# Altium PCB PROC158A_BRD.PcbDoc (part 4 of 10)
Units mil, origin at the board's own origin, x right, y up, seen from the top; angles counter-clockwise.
Board outline 3346.45 x 4921.26 mil, 8 copper layers (Top Layer, GND1, SIG1, PWR1, PWR2, SIG2, GND2, Bottom Layer), stack 54.534 mil thick; 718 components, 459 nets, 2307 pads, 1179 vias.
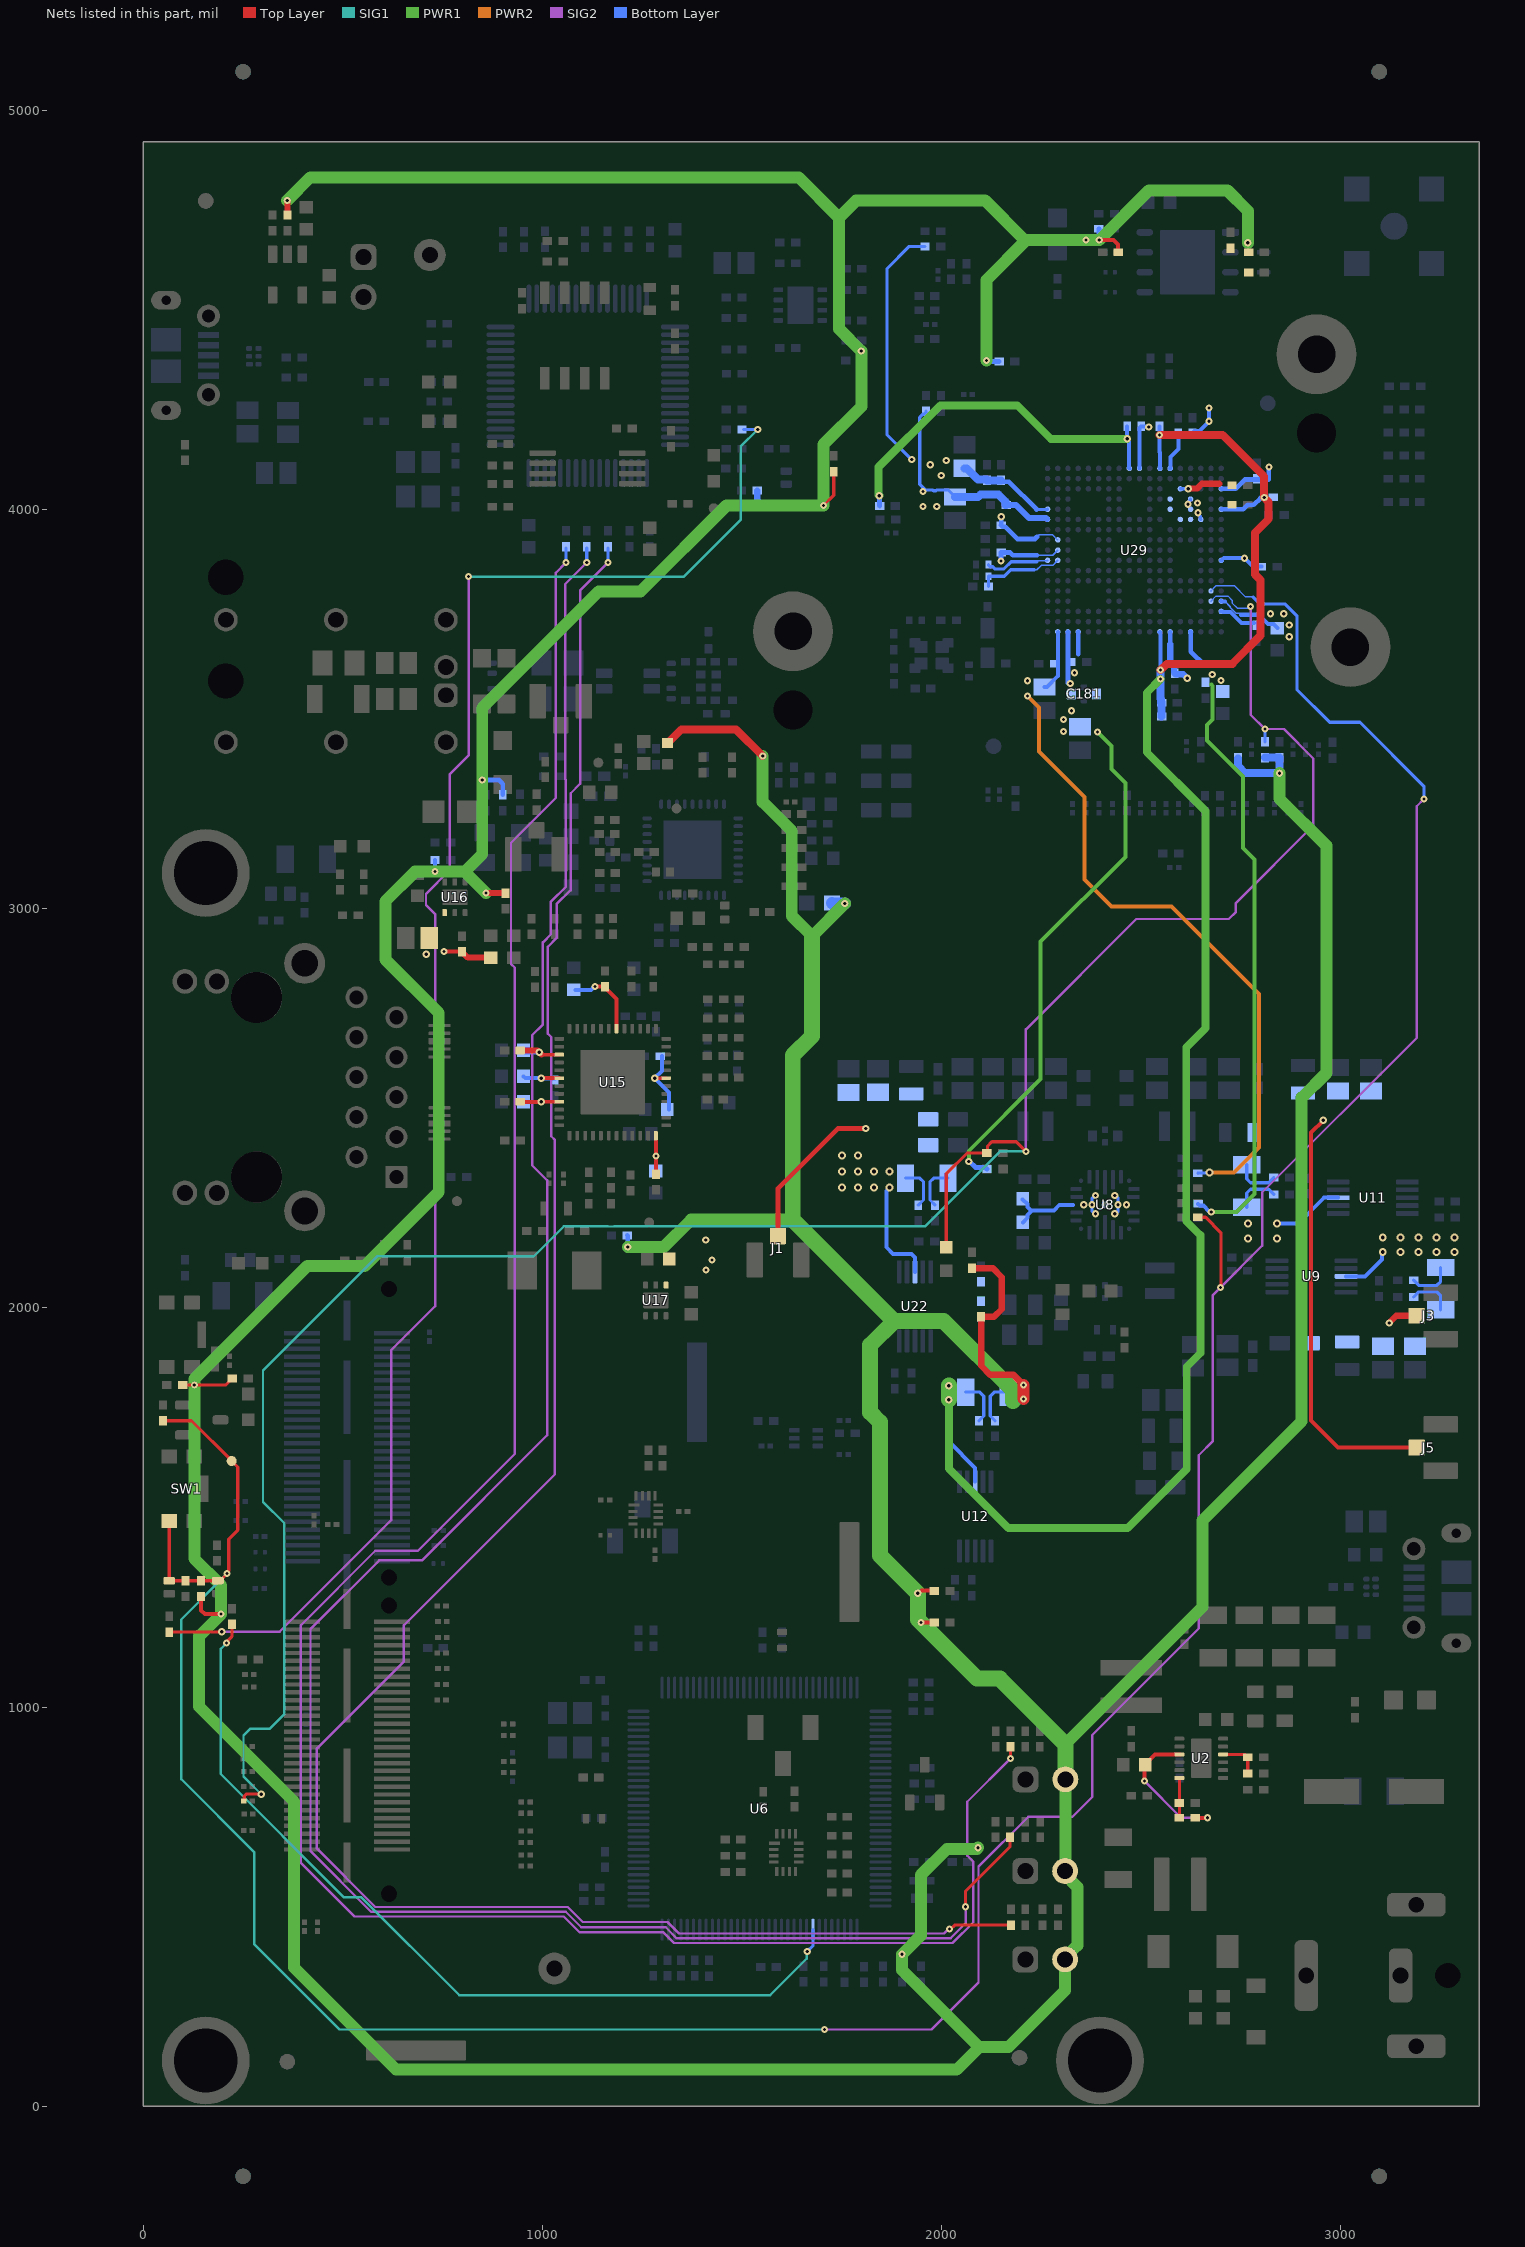
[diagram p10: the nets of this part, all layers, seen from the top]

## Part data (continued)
FB2 FB3: library part CMP-0089848-1, "600 Ohms @ 100MHz 1 Power Line Ferrite Bead 0603 (1608 Metric) 1.3A 150mOhm", Digikey Part Number=490-13259-1-ND, Impedance At Frequency="600Ω @ 100MHz", Manufacturer=Murata, Mouser Part Number=81-BLM18KG601SH1D, Operating Temperature Range="-55°C to +125°C", Test Frequency=100MHz, Tolerance_%=25%
FID1 FID2 FID3 FID4 FID5 FID6 FID7 FID8 FID9 FID10 FID11 FID12 FID13 FID14 FID15 FID16: library part CMP-0077181-1, "Fiducial mark.  There is nothing to buy or mount.", Manufacturer=N/A
J1 J3 J5: library part CMP-0091846-1, "U.FL (UMCC) Connector Jack, Male Pin 50Ohm Surface Mount Solder", Dielectric Material="Liquid Crystal Polymer", Digikey Part Number=A118077CT-ND, Frequency_Fixed=0-6GHz, Manufacturer="TE Connectivity", Mouser Part Number=571-1909763-1, Operating Temperature Range="-40°C to +90°C"
J2 J14: library part CMP-0055788-1, "UMC Straight Jack Receptacle, 50 Ohm, Gold, SMT", Manufacturer="Cinch Connectivity", Supplier Part Number 1=J983CT-ND
J4: library part CMP-0078655-1, "1 Port Header Assembly, TH", Color=Blue, Manufacturer="TE Connectivity"
J7: library part CMP-0075524-1, "Receptacle, 0.5 mm, 30x2, Gold, TH", Color=Black, Manufacturer=Samtec, Supplier Part Number 1=SAM8180-ND
J8 J10: library part CMP-0055293-1, "Connector, Receptacle, Micro-USB Type B, R/A, Bottom Mount SMT", Manufacturer=Molex, Supplier Part Number 1=WM1399CT-ND
J9: library part CMP-0088394-1, "RJ45 Connector with 1000 Base-TX Inetgrated Magnetic", Manufacturer=LINK-PP, Operating Temperature Range="-40°C to +85°C"
J12: library part CMP-0079472-1, "DC POWER JACK, R/A, TH", Color=Black, Current_A=8A, Manufacturer="CUI Inc.", Supplier Part Number 1=CP-063AH-ND, Voltage_V=24V
J13: library part CMP-0055823-2, "Connector, SMA Jack, Vertical, Gold, SMD", Color=Gold, Manufacturer="Cinch Connectivity"
J17 J18 J20 P1: library part CMP-0075405-3, "Header, 100mil, 2x1, Gold, TH", Color=Black, Current_A=6.3A, Manufacturer=Samtec, Supplier Part Number 1=SAM1029-02-ND, Voltage_V=550V
J19: library part CMP-0075524-1, "Receptacle, 0.5 mm, 30x2, Gold, TH", Color=Black, Manufacturer=Samtec, PartNumber=QSH-030-01-L-D-A, Supplier Part Number 1=SAM8180-ND
J21 J22 J23: library part CMP-0084373-1, "Header, 1x1, Gold, SMT", Color=Black, Current_A=3A, Manufacturer="Sullins Connector Solutions"
L1 L12: library part CMP-0089947-1, "100 Ohms @ 100MHz 1 Power Line Ferrite Bead 0805 (2012 Metric) 4A 20mOhm", Digikey Part Number=445-172903-1-ND, Impedance At Frequency="100Ω @ 100MHz", Manufacturer=TDK, Mouser Part Number=810-MPZ2012S101ATD25, Operating Temperature Range="-55°C to +125°C", Test Frequency=100MHz, Tolerance_%=25%
L2 L8 L9: library part CMP-0059953-1, "Inductor, 470 nH, 4 A, 0.025 ohm, SMD", Manufacturer=Cyntec, Value1="0.025 ohm", Value2=4A, ValueDisplayed=470nH
L3 L4: library part CMP-0081523-1, "Ferrite Bead, 600 ohm @ 100 MHz, 0.3 A, 0402", Manufacturer=MuRata, Supplier Part Number 1=490-3998-1-ND, Value1="0.7 ohm", Value2=0.3A, ValueDisplayed="600 ohm"
L5: library part CMP-0089502-2, "Power Inductor (SMD), 4.7 µH, 5.1 A, Shielded, 4.5 A, XAL40xx Series, 4mm x 4mm x 3.1mm", Manufacturer=Coilcraft, Mouser Part Number=994-XAL4030-472MEC, Operating Temperature Range="to +165°C", Self Resonant Frequency=36MHz, Test Frequency=1MHz, Tolerance_%=20%
L6: library part CMP-0061088-1, "Inductor, Shielded, Composite, 2.2 uH, 6.1 A, 0.0201 ohm, AEC-Q200 Grade 1, SMD", Manufacturer=Coilcraft, Value1="0.0201 ohm", Value2=6.1A, ValueDisplayed=2.2uH
L7: library part CMP-0090833-1, "100μH @ 100kHz 2 Line Common Mode Choke Surface Mount 100mA DCR 3.12Ω", Manufacturer=Murata, Mouser Part Number=81-DLW32MH101XT2L, Operating Temperature Range="-40°C to +125°C", Test Frequency=100kHz, Tolerance_%=-25/+50%
L11: library part CMP-0098175-1, "Differential Mode Choke 3.9uH 540mA 0.36Ohm 3.2x2.5x2.5mm SMT", Manufacturer=TDK, Operating Temperature Range="-40°C to +150°C", Test Frequency=100kHz, Tolerance_%=20%
LBL1: library part CMP-0003625-1, "Thermal Transfer Printable Labels, 0.650\" W x 0.200\" H - 10,000 per roll", Manufacturer=Brady, Supplier Part Number 1=97C5133
Logo1: library part CMP-0074838-1, "Texas Instrument Corporate Signature"
LOGO2: library part CMP-0074844-1
Logo3: library part CMP-0074847-1, "FCC_disclaimer"
Logo4: library part CMP-0074769-1
Logo5: library part CMP-0093808-1, Manufacturer="Texas Instruments", Operating Temperature Range=to
NT1: library part CMP-0078142-4, "Single point connection between nets.", Manufacturer=N/A
NT2 NT3 NT4: library part CMP-0078142-3, "Single point connection between nets.", Manufacturer=N/A
Q1: library part CMP-0000947-2, "MOSFET, N-CH, 100 V, 0.17 A, SOT-23", Alternate Manufacturer=None, Manufacturer="Fairchild Semiconductor", Supplier Part Number 1=BSS123NCT-ND, Value1=1, Value2="1.8 nC"
R1 R3 R4 R6 R14 R19 R20 R22 R23 R27 R28 R29 R31 R33 R35 R37 R50 R54 R55 R57 R58 R59 R62 R67 R70 R71 R76 R79 R85 R86 R87 R95 R113 R117 R128 R129 R131 R136 R146 R148 R149 R150 R151 R152 R153 R158 R162 R166 R168 R181 R186 R190 R209 R233 R241 R246 R269 R291 R295 R316 R330 R353 R354 R355 R356 R357 R358 R359 R360 R400 R401 R419: library part CMP-0026992-3, "RES, 0, 5%, 0.1 W, AEC-Q200 Grade 0, 0402", Manufacturer=Panasonic, Power_W=100mW, Supplier Part Number 1=P0.0JCT-ND, TempCo="600 ppm/C", Tolerance_%=5%, Value2=0.1W, Value_Code=0000, ValueDisplayed=0
R2: library part CMP-0026555-2, "RES, 7.50 k, 1%, 0.063 W, AEC-Q200 Grade 0, 0402", Manufacturer=Vishay-Dale, Power_W=63mW, Supplier Part Number 1=541-7.50KLCT-ND, TempCo="100 ppm/C", Tolerance_%=1%, Value2=0.063W, Value_Code=7k50, ValueDisplayed=7.50k
R5 R12 R18 R21 R24 R25 R51 R61 R72 R78 R80 R81 R82 R84 R90 R91 R94 R104 R114 R115 R135 R138 R160 R164 R165 R167 R188 R196 R197 R198 R215 R216 R218 R219 R220 R223 R224 R226 R229 R317 R318 R319 R320 R321 R322 R323 R324 R327 R328 R329 R334 R341 R344 R345 R349 R351 R361 R363 R364 R365 R366 R370 R371 R379 R390 R391 R399 R422 R423 R424 R425: library part CMP-0027008-4, "RES, 0, 5%, 0.05 W, 0201", Manufacturer=Vishay-Dale, Power_W=50mW, Supplier Part Number 1=72M6743, TempCo=ppm/C, Tolerance_%=5%, Value2=0.05W, Value_Code=0000, ValueDisplayed=0
R7 R8 R9 R10 R11 R17 R41 R43 R46 R49 R102 R125 R155 R157 R177 R184 R185 R187 R201 R222 R251 R264 R271 R272 R273 R283 R296 R299 R301 R303 R305 R309 R310 R312 R326 R335 R350 R409 R416 R417 R418: library part CMP-0025958-3, "RES, 10.0 k, 1%, 0.063 W, AEC-Q200 Grade 0, 0402", Manufacturer=Vishay-Dale, Power_W=63mW, Supplier Part Number 1=541-10.0KLCT-ND, TempCo="100 ppm/C", Tolerance_%=1%, Value2=0.063W, Value_Code=10k0, ValueDisplayed=10.0k
R13 R15 R16 R75 R92 R97 R112 R118 R132 R137 R139 R141 R142 R143 R173 R252 R253 R254 R255 R256 R257 R258 R286 R287 R288 R289: library part CMP-0026237-2, "RES, 2.49 k, 1%, 0.063 W, AEC-Q200 Grade 0, 0402", Manufacturer=Vishay-Dale, Power_W=63mW, Supplier Part Number 1=541-2.49KLCT-ND, TempCo="100 ppm/C", Tolerance_%=1%, Value2=0.063W, Value_Code=2k49, ValueDisplayed=2.49k
R26 R32 R36 R47 R56 R65 R66 R268 R348 R352 R362: library part CMP-0025964-3, "RES, 10.2, 1%, 0.063 W, AEC-Q200 Grade 0, 0402", Manufacturer=Vishay-Dale, Power_W=63mW, Supplier Part Number 1=541-10.2LCT-ND, TempCo="100 ppm/C", Tolerance_%=1%, Value2=0.063W, Value_Code=10R2, ValueDisplayed=10.2
R30 R60 R64 R346: library part CMP-0017253-2, "RES, 0.001, 1%, 1 W, AEC-Q200 Grade 0, 1206", Manufacturer="Stackpole Electronics Inc", Power_W=1W, Supplier Part Number 1=CSNL1206FT1L00CT-ND, TempCo="50 ppm/C", Tolerance_%=1%, Value_Code=1L000, ValueDisplayed=0.001
R34 R205 R280 R340 R342: library part CMP-0026890-5, "RES, 2.2 k, 5%, 0.063 W, AEC-Q200 Grade 0, 0402", Manufacturer=Vishay-Dale, Power_W=63mW, Supplier Part Number 1=541-2.2KJCT-ND, TempCo="200 ppm/C", Tolerance_%=5%, Value2=0.063W, Value_Code=2k20, ValueDisplayed=2.2k
R38: library part CMP-0026395-2, "RES, 47.5 k, 1%, 0.063 W, AEC-Q200 Grade 0, 0402", Manufacturer=Vishay-Dale, Power_W=63mW, Supplier Part Number 1=541-47.5KLCT-ND, TempCo="100 ppm/C", Tolerance_%=1%, Value2=0.063W, Value_Code=47k5, ValueDisplayed=47.5k
R39 R40 R42 R44 R45 R374 R375 R376 R377: library part CMP-0089575-2, "Res Thick Film 0201 33.2 Ohm 1% 0.05W(1/20W) ±200ppm/C Pad SMD Automotive T/R", Digikey Part Number=P122945CT-ND, Manufacturer=Panasonic, Mouser Part Number=667-ERJ-1GNF33R2C, Operating Temperature Range="-55°C to +125°C", Power_W=50mW, TempCo=200ppm/°C, Tolerance_%=1%
R48 R52 R53 R63 R106 R116 R199 R265 R270: library part CMP-0081856-1, "RES, 0, 0%, 0.2 W, AEC-Q200 Grade 0, 0402", Manufacturer=Vishay-Dale, Power_W=200mW, Supplier Part Number 1=541-0.0YBTR-ND, Tolerance_%=0%, Value2=0.2W, Value_Code=0
R68 R69: library part CMP-0026878-3, "RES, 220, 5%, 0.063 W, AEC-Q200 Grade 0, 0402", Manufacturer=Vishay-Dale, Power_W=63mW, Supplier Part Number 1=541-220JCT-ND, TempCo="200 ppm/C", Tolerance_%=5%, Value2=0.063W, Value_Code=220R, ValueDisplayed=220
R73 R183 R278 R279: library part CMP-0025950-3, "RES, 100 k, 1%, 0.063 W, AEC-Q200 Grade 0, 0402", Manufacturer=Vishay-Dale, Power_W=63mW, Supplier Part Number 1=541-100KLCT-ND, TempCo="100 ppm/C", Tolerance_%=1%, Value2=0.063W, Value_Code=100k
R74 R96 R98 R100 R101 R103 R105 R121 R122 R144 R145 R147 R169 R170 R171 R178 R179 R195 R225 R230 R234 R237 R238 R239 R240 R245 R247 R249 R290 R325 R336 R338 R339 R369 R380 R381 R386 R387 R388 R389 R413: library part CMP-0026299-2, "RES, 33.2, 1%, 0.063 W, AEC-Q200 Grade 0, 0402", Manufacturer=Vishay-Dale, Power_W=63mW, Supplier Part Number 1=541-33.2LCT-ND, TempCo="100 ppm/C", Tolerance_%=1%, Value2=0.063W, Value_Code=33R2, ValueDisplayed=33.2
R77 R93 R108 R120: library part CMP-0026699-1, "RES, 470, 1%, 0.1 W, AEC-Q200 Grade 0, 0402", Manufacturer=Panasonic, Power_W=100mW, Supplier Part Number 1=P470LCT-ND, TempCo="100 ppm/C", Tolerance_%=1%, Value2=0.1W, Value_Code=470R, ValueDisplayed=470
R83 R154 R242 R333: library part CMP-0026993-2, "RES, 100, 5%, 0.1 W, AEC-Q200 Grade 0, 0402", Manufacturer=Panasonic, Power_W=100mW, Supplier Part Number 1=P100JCT-ND, TempCo="200 ppm/C", Tolerance_%=5%, Value2=0.1W, Value_Code=100R, ValueDisplayed=100
R88 R89 R107 R109 R110 R176 R189 R192 R193 R200: library part CMP-0091690-1, "RES 0 OHM JUMPER 1/4W 0603", Digikey Part Number=HCJ0603ZT0R00CT-ND, Manufacturer="Stackpole Electronics", Operating Temperature Range="-55°C to +155°C", Power_W=250mW
R99 R123 R124 R126 R127 R133 R140 R159 R163 R315 R331: library part CMP-0026071-3, "RES, 1.00 k, 1%, 0.063 W, AEC-Q200 Grade 0, 0402", Manufacturer=Vishay-Dale, Power_W=63mW, Supplier Part Number 1=541-1.00KLCT-ND, TempCo="100 ppm/C", Tolerance_%=1%, Value2=0.063W, Value_Code=1k00, ValueDisplayed=1.00k
R111: library part CMP-0097069-1, "RES Thick Film, 4.22kΩ, 1%, 0.063W, 100ppm/°C, 0402", Manufacturer=Vishay, Operating Temperature Range="-55°C to +155°C", Power_W=63mW, TempCo=100ppm/°C, Tolerance_%=1%
R119 R130: library part CMP-0018610-3, "RES, 1.0 M, 5%, 0.25 W, AEC-Q200 Grade 0, 1206", Manufacturer=Vishay-Dale, Power_W=250mW, Supplier Part Number 1=541-1.0MECT-ND, TempCo="200 ppm/C", Tolerance_%=5%, Value2=0.25W, Value_Code=1M00, ValueDisplayed=1.0M
R134: library part CMP-0026404-2, "RES, 49.9, 1%, 0.063 W, AEC-Q200 Grade 0, 0402", Manufacturer=Vishay-Dale, Power_W=63mW, Supplier Part Number 1=541-49.9LCT-ND, TempCo="100 ppm/C", Tolerance_%=1%, Value2=0.063W, Value_Code=49R9, ValueDisplayed=49.9
R156: library part CMP-0026512-2, "RES, 6.04 k, 1%, 0.063 W, AEC-Q200 Grade 0, 0402", Manufacturer=Vishay-Dale, Power_W=63mW, Supplier Part Number 1=541-6.04KLCT-ND, TempCo="100 ppm/C", Tolerance_%=1%, Value2=0.063W, Value_Code=6k04, ValueDisplayed=6.04k
R161 R175: library part CMP-0025884-3, "RES, 0, 5%, 0.125 W, 0603", Manufacturer=Vishay/Beyschlag, Power_W=125mW, Supplier Part Number 1=MCT0603-0.0-ZZCT-ND, TempCo=ppm/C, Tolerance_%=5%, Value2=0.125W, Value_Code=0000, ValueDisplayed=0
R172: library part CMP-0025960-3, "RES, 10.5 k, 1%, 0.063 W, AEC-Q200 Grade 0, 0402", Manufacturer=Vishay-Dale, Power_W=63mW, Supplier Part Number 1=541-10.5KLCT-ND, TempCo="100 ppm/C", Tolerance_%=1%, Value2=0.063W, Value_Code=10k5, ValueDisplayed=10.5k
R174 R208: library part CMP-0078244-2, "RES, 30.0 k, 1%, 0.063 W, AEC-Q200 Grade 0, 0402", Manufacturer=Vishay-Dale, Power_W=63mW, Supplier Part Number 1=541-30.0KLCT-ND, TempCo="100 ppm/C", Tolerance_%=1%, Value2=0.063W, Value_Code=30k0, ValueDisplayed=30.0k
R180 R261 R262 R263 R266 R347: library part CMP-0078212-1, "RES, 510, 5%, 0.1 W, AEC-Q200 Grade 0, 0402", Manufacturer=Panasonic, Power_W=100mW, Supplier Part Number 1=P510JCT-ND, TempCo="200 ppm/C", Tolerance_%=5%, Value2=0.1W, Value_Code=510R, ValueDisplayed=510
R182 R206 R207: library part CMP-0020442-3, "RES, 0, 5%, 0.125 W, AEC-Q200 Grade 0, 0805", Manufacturer=Vishay-Dale, Power_W=125mW, Supplier Part Number 1=541-0.0ACT-ND, TempCo="200 ppm/C", Tolerance_%=5%, Value2=0.125W, Value_Code=0000, ValueDisplayed=0
R191: library part CMP-0091603-1, "0 Ohms Jumper 0.5W, 1/2W Chip Resistor 0805 (2012 Metric) Automotive AEC-Q200 Metal Foil", Digikey Part Number=HCJ0805ZT0R00CT-ND, Manufacturer=Stackpole, Operating Temperature Range="-55°C to +155°C", Power=500mW
R194: library part CMP-0026413-2, "RES, 4.87 k, 1%, 0.063 W, AEC-Q200 Grade 0, 0402", Manufacturer=Vishay-Dale, Power_W=63mW, Supplier Part Number 1=541-4.87KLCT-ND, TempCo="100 ppm/C", Tolerance_%=1%, Value2=0.063W, Value_Code=4k87, ValueDisplayed=4.87k
R202: library part CMP-0026403-2, "RES, 49.9 k, 1%, 0.063 W, AEC-Q200 Grade 0, 0402", Manufacturer=Vishay-Dale, Power_W=63mW, Supplier Part Number 1=541-49.9KLCT-ND, TempCo="100 ppm/C", Tolerance_%=1%, Value2=0.063W, Value_Code=49k9, ValueDisplayed=49.9k
R203: library part CMP-0026225-2, "RES, 29.4 k, 1%, 0.063 W, AEC-Q200 Grade 0, 0402", Manufacturer=Vishay-Dale, Power_W=63mW, Supplier Part Number 1=541-29.4KLCT-ND, TempCo="100 ppm/C", Tolerance_%=1%, Value2=0.063W, Value_Code=29k4, ValueDisplayed=29.4k
R204: library part CMP-0026158-2, "RES, 200 k, 1%, 0.063 W, AEC-Q200 Grade 0, 0402", Manufacturer=Vishay-Dale, Power_W=63mW, Supplier Part Number 1=541-200KLCT-ND, TempCo="100 ppm/C", Tolerance_%=1%, Value2=0.063W, Value_Code=200k
R211: library part CMP-0026468-2, "RES, 5.76 k, 1%, 0.063 W, AEC-Q200 Grade 0, 0402", Manufacturer=Vishay-Dale, Power_W=63mW, Supplier Part Number 1=541-5.76KLCT-ND, TempCo="100 ppm/C", Tolerance_%=1%, Value2=0.063W, Value_Code=5k76, ValueDisplayed=5.76k
R217 R221 R227 R228 R231 R232 R235 R236: library part CMP-0027021-3, "RES, 10, 5%, 0.05 W, 0201", Manufacturer="Yageo America", Power_W=50mW, Supplier Part Number 1=311-10NCT-ND, TempCo="350 ppm/C", Tolerance_%=5%, Value2=0.05W, Value_Code=10R0, ValueDisplayed=10
R243 R508 R512: library part CMP-0027280-3, "RES, 4.70 k, 1%, 0.05 W, 0201", Manufacturer=Vishay-Dale, Power_W=50mW, Supplier Part Number 1=541-4.70KAABCT-ND, TempCo="100 ppm/C", Tolerance_%=1%, Value2=0.05W, Value_Code=4k70, ValueDisplayed=4.70k
R244: library part CMP-0027015-3, "RES, 22, 5%, 0.05 W, AEC-Q200 Grade 1, 0201", Manufacturer=Panasonic, Power_W=50mW, Supplier Part Number 1=ERJ-1GNJ220C-ND, TempCo="200 ppm/C", Tolerance_%=5%, Value2=0.05W, Value_Code=22R0, ValueDisplayed=22
R248: library part CMP-0022138-4, "RES, 1.00 M, 1%, 0.1 W, AEC-Q200 Grade 0, 0603", Manufacturer=Vishay-Dale, Power_W=100mW, Supplier Part Number 1=541-1.00MHCT-ND, TempCo="100 ppm/C", Tolerance_%=1%, Value2=0.1W, Value_Code=1M00, ValueDisplayed=1.00M
R260 R274: library part CMP-0026210-2, "RES, 26.7, 1%, 0.063 W, AEC-Q200 Grade 0, 0402", Manufacturer=Vishay-Dale, Power_W=63mW, Supplier Part Number 1=541-26.7LCT-ND, TempCo="100 ppm/C", Tolerance_%=1%, Value2=0.063W, Value_Code=26R7, ValueDisplayed=26.7
R267: library part CMP-0026827-3, "RES, 10, 5%, 0.063 W, AEC-Q200 Grade 0, 0402", Manufacturer=Vishay-Dale, Power_W=63mW, Supplier Part Number 1=541-10JCT-ND, TempCo="200 ppm/C", Tolerance_%=5%, Value2=0.063W, Value_Code=10R0, ValueDisplayed=10
R275 R281: library part CMP-0021848-2, "RES, 1.00 k, 1%, 0.25 W, 0805", Manufacturer=Panasonic, Power_W=250mW, Supplier Part Number 1=P16058CT-ND, TempCo="100 ppm/C", Tolerance_%=1%, Value2=0.25W, Value_Code=1k00, ValueDisplayed=1.00k
R276 R277: library part CMP-0026244-2, "RES, 2.94 k, 1%, 0.063 W, AEC-Q200 Grade 0, 0402", Manufacturer=Vishay-Dale, Power_W=63mW, Supplier Part Number 1=541-2.94KLCT-ND, TempCo="100 ppm/C", Tolerance_%=1%, Value2=0.063W, Value_Code=2k94, ValueDisplayed=2.94k
R282: library part CMP-0020444-3, "RES, 100 k, 5%, 0.125 W, AEC-Q200 Grade 0, 0805", Manufacturer=Vishay-Dale, Power_W=125mW, Supplier Part Number 1=541-100KACT-ND, TempCo="200 ppm/C", Tolerance_%=5%, Value2=0.125W, Value_Code=100k
R284 R285: library part CMP-0078210-2, "RES, 330 k, 1%, 0.063 W, AEC-Q200 Grade 0, 0402", Manufacturer=Vishay-Dale, Power_W=63mW, Supplier Part Number 1=541-330KLCT-ND, TempCo="100 ppm/C", Tolerance_%=1%, Value2=0.063W, Value_Code=330k
R293: library part CMP-0022443-4, "RES, 48.7 k, 1%, 0.1 W, AEC-Q200 Grade 0, 0603", Manufacturer=Vishay-Dale, Power_W=100mW, Supplier Part Number 1=541-48.7KHCT-ND, TempCo="100 ppm/C", Tolerance_%=1%, Value2=0.1W, Value_Code=48k7, ValueDisplayed=48.7k
R294: library part CMP-0022430-4, "RES, 45.3 k, 1%, 0.1 W, AEC-Q200 Grade 0, 0603", Manufacturer=Vishay-Dale, Power_W=100mW, Supplier Part Number 1=541-45.3KHCT-ND, TempCo="100 ppm/C", Tolerance_%=1%, Value2=0.1W, Value_Code=45k3, ValueDisplayed=45.3k
R298 R304 R308: library part CMP-0026542-2, "RES, 750, 1%, 0.063 W, AEC-Q200 Grade 0, 0402", Manufacturer=Vishay-Dale, Power_W=63mW, Supplier Part Number 1=541-750LCT-ND, TempCo="100 ppm/C", Tolerance_%=1%, Value2=0.063W, Value_Code=750R, ValueDisplayed=750
R300 R306 R311: library part CMP-0026557-2, "RES, 7.87 k, 1%, 0.063 W, AEC-Q200 Grade 0, 0402", Manufacturer=Vishay-Dale, Power_W=63mW, Supplier Part Number 1=541-7.87KLCT-ND, TempCo="100 ppm/C", Tolerance_%=1%, Value2=0.063W, Value_Code=7k87, ValueDisplayed=7.87k
R302 R307 R313: library part CMP-0026574-2, "RES, 82.5 k, 1%, 0.063 W, AEC-Q200 Grade 0, 0402", Manufacturer=Vishay-Dale, Power_W=63mW, Supplier Part Number 1=541-82.5KLCT-ND, TempCo="100 ppm/C", Tolerance_%=1%, Value2=0.063W, Value_Code=82k5, ValueDisplayed=82.5k
R337: library part CMP-0025975-3, "RES, 11.0 k, 1%, 0.063 W, AEC-Q200 Grade 0, 0402", Manufacturer=Vishay-Dale, Power_W=63mW, Supplier Part Number 1=541-11.0KLCT-ND, TempCo="100 ppm/C", Tolerance_%=1%, Value2=0.063W, Value_Code=11k0, ValueDisplayed=11.0k
R414: library part CMP-0089574-2, "Res Thick Film 0603 1M Ohm 1% 1/10W ±100ppm/°C Molded SMD Paper T/R", Digikey Part Number=541-5248-1-ND, Manufacturer=Vishay, Mouser Part Number=71-CRCW06031M00FKEAC, Operating Temperature Range="-55°C to +155°C", Power_W=100mW, TempCo=100ppm/°C, Tolerance_%=1%
R503: library part CMP-0083836-1, "RES, 100, 1%, 0.05 W, 0201", Manufacturer=Vishay-Semiconductor, Power_W=50mW, TempCo="100 ppm/C", Tolerance_%=1%, Value2=0.05W, Value_Code=100R, ValueDisplayed=100
S1 S2: library part CMP-0002159-2, "Slide SW, SPDT 0.1A 50VDC", CurrentRating_mA=100A, Manufacturer="Copal Electronics", Supplier Part Number 1=563-1023-1-ND
SW1 SW2: library part CMP-0002325-1, "Switch, SPST-NO, Off-Mom, 0.01 A, 32 VDC, SMD", CurrentRating_mA=10A, Manufacturer="C&K Components", Supplier Part Number 1=401-1432-2-ND
TP1 TP2 TP3 TP4 TP5 TP6: library part CMP-0078143-3, "TEST POINT.  No entry in BOM.", Manufacturer=N/A
TP7 TP9: library part CMP-0055138-1, "Test Point, Miniature, Black, TH", Color=Black, Manufacturer=Keystone, Supplier Part Number 1=36-5001-ND
U1: library part CMP-0091081-1, "3.3V Uniform Sector Dual and Quad Serial Flash SPI 64Mbit 2.7-3.6V WSON8", Frequency_Fixed=120MHz, Manufacturer=GigaDevice, Max Supply Voltage=3.6V, Min Supply Voltage=2.7V, Nominal Supply Current=13-15mA, Operating Temperature Range="-40°C to +125°C"
U2: library part CMP-0088353-1, "3.5-V to 36-V, 1.5-A, and 2.5-A Automotive Step-down Voltage Converter", Manufacturer="Texas Instruments", Max Supply Voltage=32V, Min Supply Voltage=3.5V, Nominal Supply Current=23uA, Operating Temperature Range="-40°C to +125°C", Output Voltage=3.3/5/1-20V, Switching Frequency=400/2100/250-2200kHz
U4: library part CMP-0085268-1, "Low Power Auto PHY 1000BASE-T1 Automotive Ethernet Physical Layer Transceiver, RND0036A (VQFNP-36)", Alternate Manufacturer="Texas Instruments", Alternate PartNumber=DP83TG720SWRNDTQ1
U6: library part CMP-0029856-2, "Tiva C Series Microcontroller, 1024 KB Flash, 256 KB SRAM, 12 Bit, 20 Channels, -40 to 105 degC, 128-Pin TQFP (PDT), Green (RoHS & no Sb/Br), Tray", Manufacturer="Texas Instruments", Temperature Range="-40 to 105 degC"
U7: library part CMP-0033001-1, "Precision Micropower Shunt Voltage Reference, 0.5% accuracy, 2.5 V, 15 ppm / degC, 15 mA, -40 to 125 degC, 3-pin SOT-23 (DBZ), Green (RoHS & no Sb/Br)", Manufacturer="Texas Instruments", Rating=Catalog, Temp Coeff(Max)(ppm/ degree C)=100, Temp Coeff(Typ)(ppm/ degree C)=15
U8: library part CMP-0097513-1, "Three Buck Converters, one Linear Regulator and one Load Switch for AWR and IWR Radar Sensors, VQFN-HR24", Manufacturer="Texas Instruments", Max Supply Voltage=4/4/4/4/3.4V, Min Supply Voltage=3/3/3/1.2/1.6V, Operating Temperature Range="-40°C to +150°C", Output Voltage=0.9-1.9/0.9-1.9/0.9-1.9/0.6-3.4V
U9 U11 U12 U22: library part CMP-0098432-1, "Current Sense Amplifier 1 Circuit 10-VSSOP", Digikey Part Number=296-INA228AIDGSTCT-ND, Input Bias Current=0.01uA, Input Offset Voltage=1mV, Manufacturer="Texas Instruments", Max Supply Voltage=5.5V, Min Supply Voltage=2.7V, Mouser Part Number=595-INA228AIDGST, Nominal Supply Current=640uA, Operating Temperature Range="-40°C to +125°C"
U10 U21: library part CMP-0043115-3, "4-Channel ESD Protection Array for High-Speed Data Interfaces, DRY0006A (USON-6)", Breakdown Voltage(Min)(V)=6, IO Capacitance(Typ)(pF)=1.6, IO Leakage Current(nA)=1, Manufacturer="Texas Instruments", Operating Temperature Range="-40 to 85 C", Rating=Catalog
U13 U14: library part CMP-0073613-3, "4-Channel Ultra-Low-Capacitance IEC ESD Protection Diode, DQA0010A (USON-10)", Alternate Manufacturer="Texas Instruments"
U15: library part CMP-0076013-2, "Extended Temperature Gigabit Ethernet PHY with SGMII, RGZ0048B (VQFN-48)", Alternate Manufacturer="Texas Instruments", Alternate PartNumber=DP83867ERGZT
U16: library part CMP-0036314-5, "Single Output High PSRR LDO, 500 mA, Adjustable 1.25 to 6 V Output, 2.7 to 6.5 V Input, with Low IQ, 6-pin SON (DRV), -40 to 125 degC, Green (RoHS & no Sb/Br)", Manufacturer="Texas Instruments"
U17: library part CMP-0078869-1, "Capacitor-Free, 300-mA, Low-Dropout Regulator for Automotive, DRV0006A (WSON-6)", Alternate Manufacturer="Texas Instruments"
U18: library part CMP-0004747-1, "Quad High Speed USB to Multipurpose UART/MPSSE IC", Manufacturer=FTDI, Supplier Part Number 1=768-1026-1-ND
U19: library part CMP-0081524-1, "1K Microwire Compatible Serial EEPROM, TSSOP-8", Manufacturer=Microchip, Supplier Part Number 1=93LC46B-I/ST-ND
U20: library part CMP-0036402-3, "Single Output High PSRR LDO, 1 A, Adjustable 1.2 to 5.5 V Output, 2.7 to 5.5 V Input, 8-pin SON (DRB), -40 to 125 degC, Green (RoHS & no Sb/Br)", Manufacturer="Texas Instruments"
U23 U26: library part CMP-0067415-1, "10-Ohm Quad SPDT Analog Switch, RSV0016A (UQFN-16)", Alternate Manufacturer="Texas Instruments"
U24: library part CMP-0067397-2, "1.4V-Capable +/-0.5degC Temperature Sensor with Alert Function and I2C/SMBus interface in SOT-563, DRL0006A (SOT-OTHER-6)", Alternate Manufacturer="Texas Instruments", Alternate PartNumber=TMP112AIDRLT
U27: library part CMP-0092338-1, "Linear Voltage Regulator IC Positive Fixed Output 300mA SOT-23-5", Digikey Part Number=296-TPS78417QDBVRQ1CT-ND, Dropout Voltage=900mV, Manufacturer="Texas Instruments", Max Supply Voltage=6V, Min Supply Voltage=1.65V, Mouser Part Number=595-TPS78417QDBVRQ1, Nominal Supply Current=0.033mA, Operating Temperature Range="-40°C to +150°C", Output Voltage=1.7V
U28: library part CMP-0005318-2, "2-Kb, 4-Kb, 8-Kb and 16-Kb I2C CMOS Serial EEPROM, SOIC-8", Manufacturer="ON Semiconductor", Supplier Part Number 1=CAV24C02WE-GT3OSCT-ND
U29: library part CMP-0098489-4, Manufacturer="Texas Instruments", Operating Temperature Range=to
Y1: library part CMP-0081529-1, "Crystal, 12 MHz, 15 ppm, 8 pF, AEC-Q200 Grade 1, SMD", Frequency Stability="50 ppm", Frequency Tolerance="15 ppm", Frequency_Fixed=12MHz, Load Capacitance="8 pF", Manufacturer=NDK, Supplier Part Number 1=644-1128-1-ND
Y2: library part CMP-0078214-2, "Crystal, 16 MHz, 15 ppm, 8 pF, AEC-Q200 Grade 1, SMD", Frequency Stability="150 ppm", Frequency Tolerance="10 ppm", Frequency_Fixed=16MHz, Load Capacitance="7.36 pF", Manufacturer=NDK, Supplier Part Number 1=644-1129-1-ND
Y3: library part CMP-0001431-1, "50 MHz ±15ppm Crystal 8pF 50 Ohms 4-SMD, No Lead", Digikey Part Number=644-1306-1-ND, Frequency Stability=50ppm, Frequency Tolerance=15ppm, Frequency_Fixed=50MHz, Load Capacitance=8pF, Manufacturer=NDK, Mouser Part Number=344-NX2016SA50MSTZS3, Operating Temperature Range="-40°C to +125°C"
Y4: library part CMP-0004620-3, "Crystal, 25 MHz, 18 pF, SMD", Frequency Stability=+/-30ppm, Frequency_Fixed=25MHz, Manufacturer="Abracon Corporation", Supplier Part Number 1=535-10645-1-ND
Y5: library part CMP-0004682-5, "Crystal, 25 MHz, 12pF, AEC-Q200 Grade 1, SMD", Frequency Stability="50 ppm", Frequency_Fixed=25MHz, Load Capacitance="12 pF", Manufacturer="Abracon Corporation"
Y6: library part CMP-0001498-1, "Low Jitter, Low Power, LVCMOS Output, BAW Oscillator", Frequency Stability=20ppm, Frequency_Fixed=25MHz, Manufacturer="Texas Instruments", Max Supply Current=5mA, Max Supply Voltage=3.63V, Min Supply Voltage=1.62V, Operating Temperature Range="-40°C to +125°C"
Y7: library part CMP-0094615-2, "Crystal replacement: Ultra-low Power LVCMOS Oscillator 4-pin, VSON 3.2 x 2.5 x 0.9mm", Frequency Stability=20ppm, Frequency_Fixed=50MHz, Load Capacitance=15pF, Manufacturer="Texas Instruments", Max Supply Current=4mA, Max Supply Voltage=3.465V, Min Supply Voltage=2.375V, Operating Temperature Range="to +135°C"
ZZ1: library part CMP-0003616-3
ZZ2: library part CMP-0077236-1
ZZ3: library part CMP-0077237-1
ZZ4: library part CMP-0077238-1

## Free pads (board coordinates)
  round 220 hole 160: ""(156.55,114.56) ""(156.55,3089.06) ""(2396.55,114.56)
  round 93 hole 98 unplated: ""(1627.99,3497.95) ""(2939.16,4191.9)
  round 200 hole 94.02 mask+0: ""(1627.99,3694.8) ""(2939.17,4388.74) ""(3023.94,3655.12)

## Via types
v1: diameter 18, hole 8, Top Layer to Bottom Layer, tented both sides, 1112 vias
v2: diameter 19.68, hole 7.87, Top Layer to Bottom Layer, 28 vias
v3: diameter 20, hole 10, Top Layer to Bottom Layer, tented both sides, 26 vias
v4: diameter 16/18/18/18/18/18/18/16 (per signal layer), hole 8, Top Layer to Bottom Layer, tented both sides, 13 vias

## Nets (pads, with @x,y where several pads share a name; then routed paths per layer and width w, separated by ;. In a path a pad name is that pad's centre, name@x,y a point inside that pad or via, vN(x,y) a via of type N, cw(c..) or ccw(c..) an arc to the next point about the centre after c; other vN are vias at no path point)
1V0: C114.1 C115.2 C116.1 C117.2 C181.1 C181.3 R20.2 R56.1 R64.1 R133.2 U22.8 U29.A3 U29.A4 U29.M1 | length 2456.4
  PWR1 w10: v1(2068.09,2366.94) 2068.09,2393.6 2247.3,2572.81 2247.3,2917.3 2460,3130 2460,3315 2425.05,3349.95 2425.05,3407.65 v1(2390.1,3442.6)
  Bottom Layer w8: R64.1@1909.44,2325.21 1945.02,2325.21 1954.44,2315.79 1954.44,2270.29 R56.1@1941.56,2257.41 ; 1945.2,4063.02 1953.73,4054.49 1959.24,4048.98 1977.38,4048.98 1979.38,4046.98 1985.06,4046.98 ; 1945.2,4063.82 1945.2,4230.68 1952.89,4238.38 1954.86,4238.38 1960.71,4244.22 R133.2@1960.71,4246.19 ; v1(1953.17,4045.07) v1@1953.17,4053.92 ; 1987.06,4048.98 2015.95,4048.98 C114.1@2033.6,4031.33
  Bottom Layer w10: v3(1869.96,2301.27) 1862.09,2293.4 1862.09,2151.88 1878.66,2135.31 1924.3,2135.31 1933.06,2126.55 U22.8@1933.06,2090.17
  Bottom Layer w12: v1(2068.09,2366.94) 2069.71,2366.94 2084.99,2351.65 2109.79,2351.65 R20.2@2113.63,2347.81 ; U29.A3@2316.48,3693.52 2316.48,3565.52 2320.48,3565.52 v1(2322,3564) ; 2342.07,3637.33 U29.A4@2342.07,3693.52
  Bottom Layer w15: C115.2@2161.81,4011.14 2162.5,4011.83 2185.98,4011.83 2218.53,3979.28 2261.04,3979.28 U29.M1@2264.08,3976.24
  Bottom Layer w20: C114.1@2033.6,4031.33 2091.16,4031.33 2096.81,4036.98 2142.47,4036.98 2160,4019.45 2160,4011.29 2160.15,4011.14 C115.2@2161.81,4011.14
  other v1: 2304.9,3443.6 2304.9,3474 2325,3496 2333,3591 1953.17,4007.38 1987.71,4007.71
  other v3: 1749.96,2301.27 1789.96,2301.27 1829.96,2301.27 1749.96,2341.27 1789.96,2341.27 1829.96,2341.27 1869.96,2341.27 1749.96,2381.27 1789.96,2381.27
1V0_ETH: C56.1 C57.1 C65.1 C159.1 C160.1 C190.1 C191.1 C192.1 C193.1 U15.6 U15.24 U15.31 U15.42 U17.1 | length 628.7
  Top Layer w8: v1(1281.2,2575.38) U15.31@1309.79,2575.38
  Top Layer w10: v1(997.01,2575.38) U15.6@1042.07,2575.38 ; v1(1131.59,2804.85) 1131.78,2804.66 1156.72,2804.66 C160.1@1156.91,2804.47 ; C160.1@1156.91,2802.5 1185.77,2773.64 U15.42@1185.77,2699.4 ; C191.1@1284.2,2338.94 v1(1284.2,2380.17) U15.24@1284.2,2431.68
  Bottom Layer w10: C56.1@952.59,2580.19 957.39,2575.38 v1(997.01,2575.38) 997.68,2574.72 C57.1@1030.83,2574.72 ; C159.1@1082.48,2796.47 1121.04,2796.47 1129.43,2804.85 v1(1131.59,2804.85) ; C190.1@1284.2,2346.81 v1(1284.2,2380.17) ; C193.1@1298.94,2630.46 1298.94,2593.13 v1(1281.2,2575.38) 1316.51,2540.07 C192.1@1316.51,2497.07
  other v1: 1410,2095 1425,2120 1408.92,2169.91
1V0_FILTERED: C4.1 C151.1 C152.1 J1.1 R64.2 R66.1 R192.2 R193.2 | length 513.7
  Top Layer w12: J1.1@1590,2180 1590,2299 1740,2449 v1(1810,2449)
  Bottom Layer w8: R66.1@1983.62,2257.41 1970.74,2270.29 1970.74,2315.79 1980.15,2325.21 R64.2@2015.74,2325.21
1V2: C92.2 C96.2 C137.2 C138.2 C139.2 C140.2 C141.2 C142.2 C146.2 R26.1 R30.1 R70.2 R315.2 U9.8 U29.A15 U29.C18 U29.D18 U29.M14 U29.M15 U29.M16 U29.N13 U29.N15 U29.P13 U29.P15 U29.R14 U29.U9 U29.U13 | length 3396.4
  Top Layer w16: v1(2617.72,4052.08) 2618.1,4052.47 2639.98,4052.47 2651.8,4064.28 2695,4064.28
  PWR1 w10: v1(2675.54,2240.32) 2738.82,2240.32 2784,2285.5 2784,3122.65 2755,3151.65 2755,3331 2665,3421 2665,3460.29 2679,3474.28 2679,3557.63 2675.6,3561.03
  PWR1 w20: v1(1843.85,4034.64) 1842,4036.49 1842,4106.2 1996.9,4261.1 2189.4,4261.1 2273.5,4177 v1(2464.86,4177)
  Bottom Layer w4: 2710.3,3769.52 2723.32,3756.5 2723.32,3754.66 2738.25,3739.72 2794.95,3739.72 2797.33,3737.34
  Bottom Layer w8: v1(2464.86,4177) 2464.86,4174.84 v1@2468,4171.69 ; U29.R14@2597.98,4051.79 2598.12,4051.94 2617.58,4051.94 v1(2617.72,4052.08) ; v1(2617.45,4013.29) 2619.36,4015.2 2619.36,4020.45 2623.57,4024.65 U29.P15@2623.57,4026.2 ; v1(2642.46,3992.07) 2642.46,3989.36 2648.07,3983.75 2648.07,3976.11 U29.M16@2649.16,3975.02 ; R26.1@3182.19,2069.26 3195.07,2056.38 3240.57,2056.38 3249.98,2065.8 R30.1@3249.98,2101.38
  Bottom Layer w10: v1(2464.86,4177) C140.2@2464.86,4208.51 ; v1@2468,4171.69 2469.59,4170.1 2469.59,4103.41 U29.U9@2470.03,4102.97 ; U29.U13@2572.39,4102.97 2573.1,4103.68 2573.1,4131.47 2583.38,4141.75 2583.38,4141.88 2592.82,4151.32 C92.2@2592.82,4190.51 ; C141.2@2628.47,4190.51 2628.47,4191.58 2633.31,4196.42 2645.42,4196.42 v1(2670,4221) v1(2670,4254) ; R70.2@2642.37,2260.81 2647.21,2255.97 2655.52,2255.97 2669.63,2241.85 2674.01,2241.85 v1(2675.54,2240.32) ; U29.C18@2700.34,3744.71 2701.05,3743.99 2703.68,3743.99 2704.8,3742.87 2724.1,3742.87 2750.97,3716 C96.2@2782,3716 ; U29.D18@2700.34,3770.3 2701.05,3769.58 2710.23,3769.58 2710.3,3769.52 ; 2749.55,3735.26 2795.25,3735.26 2817.4,3713.1 2830.9,3713.1 C146.2@2841,3703 ; U9.8@3013.19,2078.86 3060.99,2078.86 3103.09,2120.96 3103.09,2137.9 v3(3105,2139.81)
  Bottom Layer w12: v1(1843.85,4034.64) 1844.3,4034.19 1844.3,4009.42 R315.2@1844.75,4008.97 ; U29.A15@2623.57,3693.52 2623.9,3693.19 2623.9,3644.1 2657.26,3610.74
  other v1: 2700,3572 2678,3587 2871,3681 2871,3711 2824,3739 2857,3739 2641,4016
  other v3: 3150,2139.81 3195,2139.81 3240,2139.81 3285,2139.81 3105,2176.81 3150,2176.81 3195,2176.81 3240,2176.81 3285,2176.81
1V2_FILTERED: C128.1 C154.1 C182.1 J3.1 R30.2 R32.1 R110.2 | length 188.7
  Top Layer w16: v1(3121.22,1962.37) 3138.85,1980 J3.1@3190,1980
  Bottom Layer w8: R32.1@3182.19,2027.2 3195.07,2040.08 3240.57,2040.08 3249.98,2030.66 R30.2@3249.98,1995.08
1V4_APLL: C55.2 C103.1 U29.H2 | length 215.6
  Bottom Layer w4: 2232.82,3848.94 2238.28,3848.94 2249.2,3859.86 2278.1,3859.86 U29.H2@2290.89,3872.66
  Bottom Layer w8: C55.2@2117.4,3807.08 C103.1@2117.4,3832.66 2156.66,3832.66 2172.94,3848.94 2232.82,3848.94
1V4_SYNTH: C102.1 U29.H1 | length 162.5
  Bottom Layer w4.5: 2238.73,3869.15 2241.24,3871.67 2264.31,3871.67 U29.H1@2265.3,3872.66
  Bottom Layer w8: C102.1@2117.4,3862.19 2117.4,3860.22 2121.28,3856.35 2128.15,3856.35 2133.25,3851.25 2156.16,3851.25 2174.06,3869.15 2238.73,3869.15
1V8: C5.2 C107.2 C110.1 C111.2 C112.1 C113.2 C163.2 C164.2 C165.2 C168.2 C170.2 R47.1 R60.1 R67.2 R156.2 U11.8 U29.A2 U29.A13 U29.H18 U29.J2 U29.K2 U29.N1 U29.R18 U29.U10 | length 3864.2
  PWR2 w10: v1(2215,3533) 2244.2,3503.8 2244.2,3393.8 2358,3280 2358,3072.6 2425.3,3005.3 2575.42,3005.3 2794.8,2785.92 2794.8,2401.5 2732.5,2339.2 v3(2671.54,2339.2)
  Bottom Layer w4: 2238.73,3885.42 2278.06,3885.42 U29.J2@2290.89,3898.25 ; 2238.73,3931.16 2244.17,3936.6 2277.67,3936.6 2290.43,3923.84 U29.K2@2290.89,3923.84
  Bottom Layer w8: v1(1925.26,4124.9) 1863.08,4187.08 1863.08,4603.08 1918.95,4658.95 R156.2@1958.29,4658.95 ; 2237.69,4000.28 2264.97,4000.28 U29.N1@2265.3,4000.61 ; R67.2@2642.1,2337.21 2643.09,2338.21 2670.55,2338.21 v3(2671.54,2339.2) ; R60.1@2764.26,2252.29 2764.26,2287.88 2773.68,2297.29 2819.17,2297.29 R47.1@2832.06,2284.41
  Bottom Layer w10: C110.1@2257.86,3555.51 2263.76,3555.51 2290.89,3582.64 2290.89,3643.25 2290.96,3643.32 2290.96,3662.03 2290.96,3662.51 2290.96,3667.53 2290.89,3667.59 U29.A2@2290.89,3693.52 ; U29.U10@2495.62,4102.97 2495.62,4204.11 C163.2@2500.01,4208.51 2500.76,4207.75 2518.25,4207.75 v1(2519,4207) ; U29.H18@2700.34,3872.66 2701.35,3872.66 2706.69,3878 v1(2759,3878) 2780.34,3856.66 C170.2@2800.86,3856.66 ; v3(2839.87,2211.81) 2893.37,2211.81 2957.47,2275.91 U11.8@2993.39,2275.91
  Bottom Layer w12: v1@2148.98,3871.02 C111.2@2148.95,3892.34 2149.25,3892.03 2171.73,3892.03 2178.35,3885.42 2238.73,3885.42 ; C5.2@2149,4073.16 2152.65,4069.51 2168.46,4069.51 2237.69,4000.28 ; v1(2149.38,3981.75) 2149.17,3981.53 2149.17,3960.95 2148.82,3960.61 2152.79,3956.64 2159.06,3956.64 2189.4,3926.3 2233.87,3926.3 2238.73,3931.16 ; 2572.45,3662.03 U29.A13@2572.39,3693.52 ; U29.R18@2700.34,4051.79 2700.81,4051.79 2701.14,4052.12 2736.88,4052.12 2760.02,4075.26 2818.1,4075.26 2818.86,4074.51 ; 2817.1,4075.46 2819.59,4077.94 2819.59,4106.07 v1(2819.96,4106.45)
  Bottom Layer w16: 2572.45,3662.03 2572.45,3615.98 2582.16,3606.27 2582.16,3591.53 C164.2@2584,3589.69 2584,3588.99 2585.84,3587.15 2605.06,3587.15 v1(2615.05,3577.16)
  Bottom Layer w20: C112.1@2057,4103 2062.91,4103 2090.94,4074.97 2113.84,4074.97 2114,4074.81 C113.2@2114,4073.16 C5.2@2149,4073.16
  other v1: 2215,3571 2149,3871 1998.9,4085.54 1971.4,4112.32 2011.5,4122.9
  other v3: 2767,2173.81 2839.87,2173.81 2767,2211.81
1V8_FILTERED: C169.1 C194.1 C198.1 J5.1 L12.2 R60.2 R65.1 | length 1170.4
  Top Layer w10: v1(2956,2469.81) 2925,2438.81 2925,1718 2993,1650 J5.1@3190,1650
  Bottom Layer w8: R60.2@2764.26,2358.59 2764.26,2323.01 2773.68,2313.59 2819.17,2313.59 R65.1@2832.06,2326.47
2V5_ETH: C34.1 C38.1 C59.1 C187.1 C188.1 C189.1 R293.2 U15.3 U15.9 U16.1 | length 394.5
  Top Layer w9: v1(997.01,2516.33) U15.9@1042.07,2516.33 ; v1@997.75,2634.44 U15.3@1042.07,2634.44
  Top Layer w10: v1(753.26,2892.91) 753.79,2892.37 797.76,2892.37 C34.1@798.3,2891.84 ; C188.1@948.66,2516.33 v1(997.01,2516.33)
  Top Layer w15: C34.1@798.3,2891.84 812.92,2877.21 R293.2@870.42,2877.21 ; C189.1@944.72,2645.15 987.04,2645.15 v1@997.75,2634.44
  Bottom Layer w10: C187.1@952.59,2645.15 957.93,2639.81 v1@985.59,2639.81 ; C59.1@956.53,2516.33 v1(997.01,2516.33)
  other v1: 992.04,2640.15 709.05,2885.81
3V3: C174.2 C175.2 C176.2 C177.2 R346.1 R348.1 U12.8 U29.A12 U29.N18 U29.U12 | length 4832.9
  Top Layer w20: v1(2546.01,4186.41) 2704.04,4186.41 2808.13,4082.32 v1(2808.13,4029.9) 2819,4019.03 2819,3975.6 2785.16,3941.76 2785.16,3837.02 2799,3823.18 2799,3684.28 2728.09,3613.37 2630.61,3613.37 2598.02,3613.37 2564.2,3613.37 v1@2548.57,3597.73
  PWR1 w20: v1(2018,1770) 2018,1597.79 2167.79,1448 2465.69,1448 2614,1596.31 2614,1852.4 2648,1886.4 2648,2182 2612.77,2217.23 2612.77,2652.33 2661,2700.56 2661,3244.95 2513.9,3392.05 2513.9,3540.88 v1(2548.44,3575.42)
  PWR1 w40: v1(2018,1770) v1(2018,1805)
  Bottom Layer w8: R346.1@2060.47,1788.99 2095.49,1788.99 2105.47,1779 2105.47,1729.21 R348.1@2093.62,1717.36
  Bottom Layer w10: v1(2018,1770) 2018,1664.71 2083.93,1598.78 2083.93,1564.58 U12.8@2084,1564.51 ; C176.2@2546.16,4208.51 2546.09,4208.43 2546.09,4186.48 v1(2546.01,4186.41) 2546.01,4144.1 2546.8,4143.31 U29.U12@2546.8,4102.97 ; U29.A12@2546.8,3693.52 2547.51,3692.81 2547.51,3690.18 2548.44,3689.25 v1(2548.44,3597.73)
  Bottom Layer w12: U29.N18@2700.34,4000.61 2755.49,4000.61 2766.65,4011.78 2781.88,4011.78 2798.85,4028.75 2806.98,4028.75 v1(2808.13,4029.9)
  Bottom Layer w20: v1@2548.44,3597.6 2548.44,3526.61 2549.5,3525.55 2549.5,3516.16 2549.66,3516 C177.2@2551.31,3516 C175.2@2551.31,3481.13
3V3_VIO: FB1.1 FB3.1 J17.2 J18.2 J20.2 R37.1 R38.2 R41.2 R43.2 R49.2 R73.2 R75.2 R79.1 R116.2 R177.1 R199.2 R261.2 R262.2 R263.2 R264.2 R271.2 R272.2 R273.2 R276.2 R277.2 R278.2 R279.2 R280.2 R295.2 R301.2 R309.2 R333.2 R346.2 R352.1 R409.2 | length 21089.2
  Top Layer w8: R333.2@98.52,1807.13 v1(127.97,1807.13) 207.37,1807.13 R263.2@223.1,1822.86 ; v1(1704,4010) 1729.69,4035.69 R261.2@1729.69,4095.04
  Top Layer w10: R264.2@144.45,1276.96 144.45,1242.47 154.11,1232.81 v1(195,1232.81) ; v1(1940.19,1284.93) 1942.36,1284.93 1948.92,1291.48 R277.2@1981.15,1291.48 ; v1(1948,1212) R276.2@1981.63,1212 ; v1(2394.83,4674.96) 2430.58,4674.96 2442.23,4663.32 2442.23,4644.89 R41.2@2442.78,4644.33
  Top Layer w15: v1(360.61,4774.11) 360.99,4773.74 360.99,4738.07 R409.2@361.36,4737.7 ; v1@859.24,3038.71 R295.2@907.18,3038.71
  Top Layer w16: R262.2@2076.38,2099.73 2127.62,2099.73 2150.67,2076.68 2150.67,1996.89 2131.22,1977.44 R199.2@2099,1977.44 2099,1855 2122,1832 2180,1832 v1(2205,1807)
  Top Layer w20: FB3.1@1313,3414.96 1313.98,3414.96 1347.84,3448.82 1485.18,3448.82 v1(1551.74,3382.25)
  Top Layer w30: v1(2205,1772) v1(2205,1807)
  PWR1 w30: v1(360.61,4774.11) 418.5,4832 1642.02,4832 1743,4731.02 ; v1(858.85,3039.11) 805.15,3092.81 ; v1(1213.68,2152.38) 1303.69,2152.38 1372.26,2220.95 1627,2220.95 ; v1(1551.74,3382.25) 1551.74,3267.66 1624.53,3194.87 1624.53,2981.76 1675.38,2930.91 v1(1757.46,3012.99) ; v1(2091,647.81) 2088.19,645 2013.66,645 1948,579.34 1948,427.81 v1(1901,380.81) 1901,341.18 1971.18,271 2094.18,148 2167,148 2309.53,290.53 J17.2@2309.53,367.91 2309.53,372.57 2339.92,402.97 2339.92,549.32 J18.2@2309.53,579.71 ; 2093.97,148 2037.52,91.56 633.68,91.56 378.17,347.06 378.17,762.83 140,1001 140,1177.81 v1(195,1232.81) 195,1304.59 127.97,1371.62 v1(127.97,1807.13) 127.97,1821.96 410.99,2104.98 554.81,2104.98 740.23,2290.4 740.23,2738.87 606.3,2872.8 606.3,3018.3 680.81,3092.81 v1(731,3092.81) 805.15,3092.81 ; v1(2112.54,4373.47) 2112.54,4575.27 2210.13,4672.87 ; J18.2@2309.78,589.42 J20.2@2309.78,818.98 ; 2309.78,907.22 2653.01,1250.45 2653.01,1467.01 2902,1716 2902,2526.55 2963.95,2588.51 2963.95,3157.79 2846,3275.74 2846,3339.3 v1(2846.1,3339.4) ; v1(2767,4668) 2767,4748 2716,4799 2518.87,4799 v1(2394.83,4674.96) v1(2361.31,4674.96) 2208.04,4674.96 2109,4774 1785.99,4774 1743,4731.02 ; 805.15,3092.81 849.18,3136.85 v1(849.18,3322.2) 849.18,3327.2 849.18,3503.18 1141,3795 1246,3795 1461,4010 v1(1704,4010) 1704,4163 1798.71,4257.71 v1(1798.71,4396.7) 1743,4452.41 1743,4731.02
  PWR1 w40: 1675.38,2930.91 1675.38,2681.15 1627,2632.77 1627,2220.95 1880.9,1967.05 ; 2179,1767 2179,1793 2004.95,1967.05 1880.9,1967.05 ; J20.2@2309.78,818.98 2309.78,907.22 2146,1071 2089,1071 1940.19,1219.81 v1(1940.19,1284.93) 1845,1380.12 1845,1714.15 1820.89,1738.26 1820.89,1907.04 1880.9,1967.05
  Bottom Layer w8: R352.1@2133.62,1717.36 2121.77,1729.21 2121.77,1779 2131.76,1788.99 R346.2@2166.77,1788.99
  Bottom Layer w10: R79.1@730.76,3121.72 730.88,3121.6 730.88,3092.93 v1(731,3092.81) ; v1(1798.71,4396.7) 1799.2,4396.21 1799.2,4373.3 R73.2@1799.69,4372.81
  Bottom Layer w12: v1(849.18,3322.2) 891.24,3322.2 900.67,3312.78 R177.1@900.67,3285.18 ; R280.2@1212.4,2181.7 1213.68,2180.42 v1(1213.68,2152.38) ; R75.2@1550.61,3354.5 1551.17,3355.07 1551.17,3381.68 v1(1551.74,3382.25) ; R309.2@1901,350.56 v1(1901,380.81) ; R301.2@2064.84,647.92 2064.89,647.86 2090.95,647.86 v1(2091,647.81) ; v1(2112.54,4373.47) 2115,4371 R273.2@2144,4371 ; R37.1@2393.63,4703.33 2394.23,4702.73 2394.23,4675.56 v1(2394.83,4674.96)
  Bottom Layer w16: R278.2@1538.04,4047.24 1538.1,4047.18 1538.1,4023.71 1552.03,4009.78 1703.78,4009.78 v1(1704,4010)
  Bottom Layer w20: R279.2@2742.16,3376.83 2742.16,3357.72 2760.48,3339.4 v1(2846.1,3339.4) 2846,3339.5 R272.2@2846,3378.64 R271.2@2810,3378.64
  Bottom Layer w30: FB1.1@1725.37,3013.81 1726.2,3012.99 v1(1757.46,3012.99)
3V3REG_ENA: R7.2 R8.1 U2.10 | length 104.4
  Top Layer w8: U2.10@2705.09,881.37 2757.97,881.37 2767,872.34 R8.1@2767,833.56
3V3REG_MODE: R9.1 R10.2 U2.6 | length 99.7
  Top Layer w8: R9.1@2595.64,722.58 2595.64,736.42 R10.2@2595.64,759.44 U2.6@2595.64,822.31
3V3REG_VCC: C10.1 R9.2 U2.3 | length 366.5
  Top Layer w10: v1(2508,814.46) 2508,853.83 C10.1@2509.54,855.36 2509.54,856.35 2534.56,881.37 U2.3@2595.64,881.37 ; R9.2@2635.01,722.58 v1(2666.24,722.58)
  SIG2 w6: v1(2508,814.46) 2599.88,722.58 v1(2666.24,722.58)
+3.3VD: R106.2 R116.1
AGND: C3.1 C123.1 NT1.2 NT2.1 NT3.1 NT4.1 U8.4-16 | length 296.5
  Bottom Layer w8: v1@2385.35,2235.02 2383.87,2235.02 2376.95,2241.93 v1(2376.95,2258.31) 2376.95,2274.7 2383.87,2281.61 v1(2385.35,2281.61) ; v1@2433.61,2235.02 2435.1,2235.02 2442.01,2241.93 v1(2442.01,2258.31) 2442.01,2274.7 2435.1,2281.61 v1(2433.61,2281.61)
  Bottom Layer w10: C3.1@2203.02,2271.47 2214.76,2259.72 2214.76,2253.08 2224.85,2243 2214.76,2232.92 2214.76,2225.77 C123.1@2203.33,2214.34 ; 2223.94,2243.9 2280.9,2243.9 2295.31,2258.31 2328.77,2258.31
  other v1: 2385.35,2235.61 2433.61,2235.61 2355.96,2258.31 2463,2258.31
AR_NERROUT: DS2.2 R54.1 R271.1 R379.1 U29.D17 | length 5851.4
  Top Layer w8: R379.1@251.34,764.55 253,766.21 253,777.24 257.69,781.92 295.26,781.92 v1(295.43,781.75) ; DS2.2@2011.69,2151.96 2011.69,2336 2063.5,2387.81 R54.1@2113.32,2387.81 2114.82,2389.32 2114.82,2404.97 2125.84,2415.98 2187.02,2415.98 v1(2211,2392)
  SIG1 w6: v1(295.43,781.75) 251,826.18 251,929 267.32,945.32 316.2,945.32 353.42,982.54 353.42,1460.58 300,1514 300,1843 585.87,2128.87 978.33,2128.87 1053.46,2204 1163.85,2204 1164.04,2203.81 1178.95,2203.81 1179.14,2204 1958,2204 2146,2392 v1(2211,2392)
  SIG2 w6: v1(2211,2392) 2211,2697.56 2487.62,2974.18 2719.15,2974.18 2737,2992.03 2737,3014 2931,3208 2931,3376.23 2857.22,3450 v1(2810,3450) 2774,3486 v1(2774,3757)
  Bottom Layer w4: U29.D17@2674.75,3770.3 2687.51,3783.06 2717.37,3783.06 2727.51,3772.92 2727.51,3765.94 2740.87,3752.58 2765.79,3752.58 2770.21,3757 v1(2774,3757)
  Bottom Layer w8: R271.1@2810,3418.01 v1(2810,3450)
AR_NRST: C105.2 D2.2 D4.2 R99.1 R264.1 R266.1 SW1.4 TP4.1 U29.E17 | length 8408.1
  Top Layer w8: R266.1@49.46,1717.26 120.8,1717.26 TP4.1@221.49,1616.57 236.65,1601.41 236.65,1443.25 214,1420.6 214,1341.04 209.89,1336.93 v1(209.89,1334.23) 209.83,1334.23 192.41,1316.81 D2.2@187,1316.81 186.76,1316.57 144.69,1316.57 R264.1@144.45,1316.33 C105.2@105.96,1316.33 D4.2@64.98,1316.33 SW1.4@64.98,1466.29 ; R99.1@2642.1,2226.96 2661.24,2226.96 2699.61,2188.58 2699.61,2052.15 v1(2698.89,2051.42)
  SIG1 w6: v1(209.89,1334.23) 95,1219.34 95,819.52 277.77,636.76 277.77,406.15 491.56,192.36 v1(1706.54,192.36)
  SIG2 w6: v1(1706.54,192.36) 1974.36,192.36 2092.27,310.27 2092.27,600.27 2216.81,724.81 2327,724.81 2377.33,775.14 2377.33,930.07 2644,1196.74 2644,1630.81 2679.59,1666.41 2679.59,2032.13 v1(2698.89,2051.42) 2803.33,2155.87 2803.33,2289.68 3190.1,2676.45 3190.1,3256.8 v1(3208.1,3274.8)
  Bottom Layer w4: U29.E17@2674.75,3795.89 2687.55,3808.68 2733.36,3808.68 2761.04,3781 2779.84,3781
  Bottom Layer w8: 2779.84,3781 2797.73,3763.1 2860.9,3763.1 2890,3734 2890,3549 2972,3467 3048,3467 3208.1,3306.9 v1(3208.1,3274.8)
AR_NRST_FTDI: R166.2 R268.1 | length 4156
  Top Layer w8: R268.1@64.98,1187.63 65.47,1188.12 195.97,1188.12 v1(196.46,1188.62)
  SIG1 w6: v1(815,3831.81) 1354.48,3831.81 1496.52,3973.85 1496.52,4157.7 v1(1539.43,4200.6)
  SIG2 w6: v1(196.46,1188.62) 196.59,1188.49 341.42,1188.49 621,1468.06 621,1894 731.15,2004.15 731.15,2986.67 708.16,3009.65 708.16,3036.97 767.39,3096.2 767.39,3336.4 815,3384.01 v1(815,3831.81)
  Bottom Layer w8: R166.2@1503.74,4200.6 v1(1539.43,4200.6)
AR_NRST_XDS: R36.1 U6.40 | length 2200.9
  Top Layer w8: v1(208.82,1160.6) 208.82,1163.23 222,1176.41 R36.1@222,1207.44
  SIG1 w6: v1(208.82,1160.6) 194,1145.78 194,832.36 503.26,523.1 546.76,523.1 791.45,278.41 1117,278.41 1570.65,278.41 1662.1,369.86 1662.1,386.57 v1(1663.4,387.86)
  Bottom Layer w8: v1(1663.4,387.86) 1663.4,387.99 1677.64,402.24 U6.40@1677.64,442.24
AR_SOP0_FTDI: R171.2 R308.2 | length 5918.1
  Top Layer w8: v1(2172.54,871.29) R308.2@2172.54,900.17
  SIG2 w6: v1(1058.91,3867.06) 1033.16,3841.31 1033.16,3277.2 921.31,3165.35 921.31,2861.82 930.62,2852.51 930.62,1633.94 688.15,1391.46 581.3,1391.46 394.93,1205.09 394.93,609.53 529.18,475.27 1053.5,475.27 1093.3,435.46 1117,435.46 1303.34,435.46 1329.93,408.88 1986,408.88 2027.31,408.88 2079,460.57 2079,613 2064.06,627.94 2064.06,762.81 v1(2172.54,871.29)
  Bottom Layer w8: v1(1058.91,3867.06) R171.2@1058.91,3902.95
AR_SOP1_FTDI: R170.2 R304.2 | length 5654.1
  Top Layer w8: v1(2060,500) 2060,539.21 2171.6,650.81 R304.2@2171.6,673.54
  SIG2 w6: v1(1111.12,3867.06) 1057.19,3813.13 1057.19,3324.36 1058.71,3322.84 1058.71,3055.12 1021.22,3017.63 1021.22,2935.8 1001.08,2915.66 1001.08,2710.08 974.04,2683.04 974.04,2647.6 974.04,2357.32 1011.96,2319.4 1011.96,1681.34 698.09,1367.46 591.24,1367.46 418.93,1195.15 418.93,639.14 570.8,487.27 1058.47,487.27 1097.33,448.41 1117,448.41 1308.68,448.41 1336.21,420.88 1986,420.88 2022.33,420.88 2060,458.54 v1(2060,500)
  Bottom Layer w8: v1(1111.12,3867.06) R170.2@1111.12,3902.95
AR_SOP2_FTDI: R169.2 R298.2 | length 5409.9
  Top Layer w8: v1(2020,444) 2022.71,444 2032.43,453.72 R298.2@2173.8,453.72
  SIG2 w6: v1(1164.49,3867.06) 1094.26,3796.82 1094.26,3312.89 1070.71,3289.34 1070.71,3046.59 1035.46,3011.35 1035.46,2926.66 1013.08,2904.28 1013.08,2687.15 1022.04,2678.19 1022.04,2429.74 1031.02,2420.77 1031.02,1583.05 653,1205.04 653,1114.43 435,896.43 435,645.58 581.31,499.27 1063.44,499.27 1101.12,461.59 1117,461.59 1313.31,461.59 1342.03,432.88 1986,432.88 2005.67,432.88 2016.79,444 v1(2020,444)
  Bottom Layer w8: v1(1164.49,3867.06) R169.2@1164.49,3902.95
